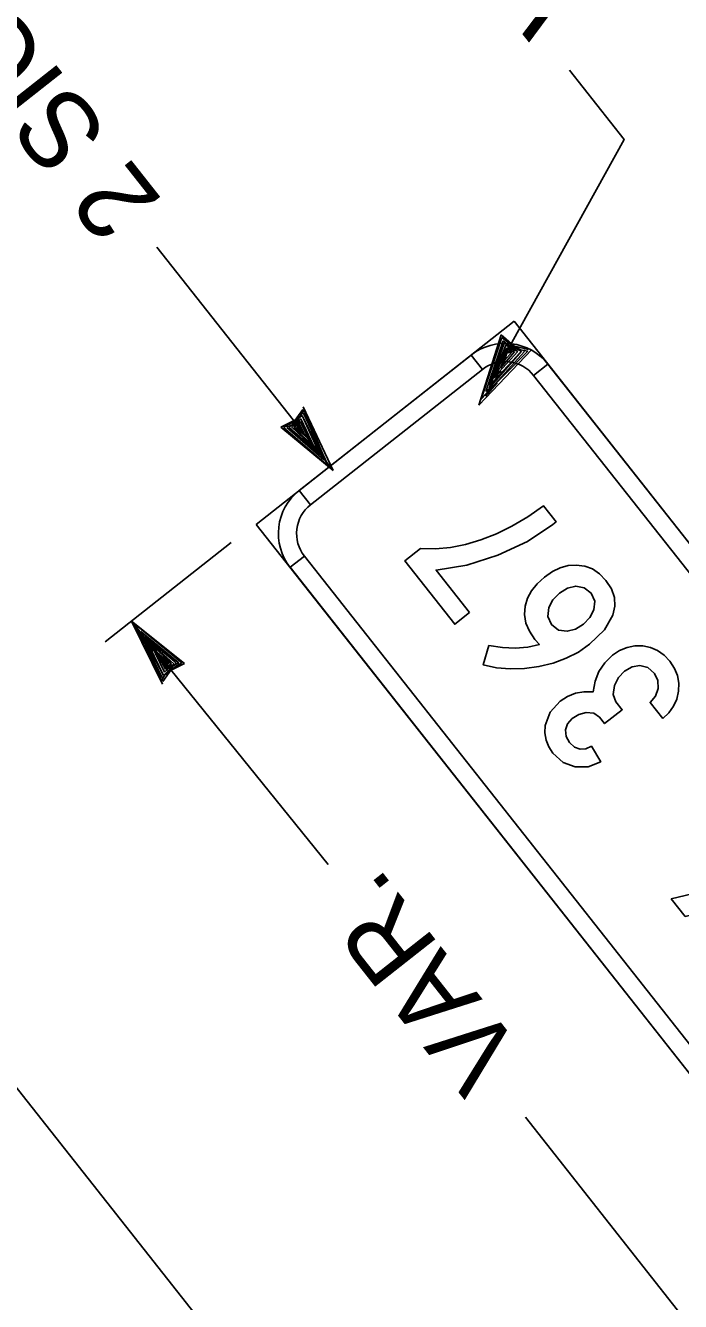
# Model space of a CAD drawing. Extents: x 672239 to 673995, y 1673540 to 1675195.
# Drawn here: x 672345.2 to 672381.1, y 1674877.9 to 1674947.8 of the extents above; entities that cross this region are included whole.
import ezdxf

# ---------------------------------------------------------------- set-up
doc = ezdxf.new("R2010")
doc.units = 0
for name, color, linetype in [('C-ALGN-SYMB', 7, 'Continuous'), ('C-ANNO-SYMB', 7, 'Continuous'), ('C-HELI-SIDE', 7, 'Continuous')]:
    doc.layers.add(name, color=color, linetype=linetype)

msp = doc.modelspace()

# ---------------------------------------------------------------- linework, layer by layer
at = {"layer": 'C-ALGN-SYMB'}
for p, q in [((672362.095, 1674923.445), (672352.437, 1674935.696)), ((672370.092, 1674927.027), (672371.308, 1674930.893)), ((672370.221, 1674927.352), (672371.348, 1674930.735)), ((672370.47, 1674927.77), (672371.412, 1674930.563)), ((672370.653, 1674927.957), (672371.559, 1674930.31)), ((672370.677, 1674928.111), (672371.465, 1674930.43)), ((672371.308, 1674930.893), (672372.005, 1674930.276)), ((672371.348, 1674930.735), (672371.917, 1674930.295)), ((672371.412, 1674930.563), (672371.654, 1674930.353)), ((672371.465, 1674930.43), (672372.431, 1674929.988)), ((672371.559, 1674930.31), (672372.226, 1674929.977)), ((672371.654, 1674930.353), (672372.431, 1674929.988)), ((672371.917, 1674930.295), (672372.784, 1674930.077)), ((672372.005, 1674930.276), (672372.372, 1674930.056)), ((672372.984, 1674930.076), (672370.092, 1674927.027)), ((672372.582, 1674929.962), (672370.251, 1674927.401)), ((672372.765, 1674929.988), (672370.378, 1674927.557)), ((672372.431, 1674929.988), (672370.653, 1674927.957)), ((672372.431, 1674929.988), (672370.677, 1674928.111)), ((672370.984, 1674928.626), (672371.56, 1674930.142)), ((672372.226, 1674929.977), (672370.984, 1674928.626)), ((672371.272, 1674929.051), (672371.574, 1674929.999)), ((672372.045, 1674929.953), (672371.272, 1674929.051)), ((672371.614, 1674930.178), (672371.398, 1674929.209)), ((672371.916, 1674929.961), (672371.497, 1674929.483)), ((672371.497, 1674929.483), (672371.634, 1674929.933)), ((672371.56, 1674930.142), (672372.045, 1674929.953)), ((672371.574, 1674929.999), (672371.916, 1674929.961)), ((672372.102, 1674930.05), (672371.614, 1674930.178)), ((672371.634, 1674929.933), (672371.743, 1674929.899)), ((672371.743, 1674929.899), (672372.102, 1674930.05)), ((672372.372, 1674930.056), (672372.765, 1674929.988)), ((672372.536, 1674930.056), (672372.582, 1674929.962)), ((672371.18, 1674929.007), (672370.949, 1674928.512)), ((672370.949, 1674928.512), (672371.31, 1674928.894)), ((672371.398, 1674929.209), (672371.18, 1674929.007)), ((672370.45, 1674927.512), (672371.096, 1674928.257)), ((672371.096, 1674928.257), (672370.47, 1674927.77)), ((672359.955, 1674926.133), (672360.442, 1674926.794)), ((672360.317, 1674926.437), (672360.512, 1674926.748)), ((672360.442, 1674926.794), (672360.374, 1674926.576)), ((672360.464, 1674926.941), (672362.095, 1674923.445)), ((672360.512, 1674926.748), (672361.744, 1674923.873)), ((672359.235, 1674925.826), (672360.003, 1674926.202)), ((672359.383, 1674925.804), (672359.955, 1674926.133)), ((672359.683, 1674925.797), (672360.395, 1674926.463)), ((672359.814, 1674925.931), (672360.395, 1674926.463)), ((672359.818, 1674925.835), (672360.333, 1674926.285)), ((672360.228, 1674926.206), (672359.949, 1674925.836)), ((672359.961, 1674925.777), (672360.29, 1674926.124)), ((672360.003, 1674926.202), (672360.317, 1674926.437)), ((672360.087, 1674925.739), (672360.238, 1674926.017)), ((672360.231, 1674925.848), (672360.228, 1674926.206)), ((672360.238, 1674926.017), (672360.499, 1674925.495)), ((672360.29, 1674926.124), (672360.787, 1674925.153)), ((672360.333, 1674926.285), (672361.048, 1674924.76)), ((672360.374, 1674926.576), (672360.47, 1674926.583)), ((672360.395, 1674926.463), (672361.378, 1674924.319)), ((672360.395, 1674926.463), (672361.5, 1674924.245)), ((672360.47, 1674926.583), (672361.833, 1674923.71)), ((672362.095, 1674923.445), (672359.235, 1674925.826)), ((672361.864, 1674923.667), (672359.383, 1674925.804)), ((672359.552, 1674925.798), (672359.814, 1674925.931)), ((672361.595, 1674924.024), (672359.552, 1674925.798)), ((672361.378, 1674924.319), (672359.683, 1674925.797)), ((672361.5, 1674924.245), (672359.818, 1674925.835)), ((672359.949, 1674925.836), (672360.697, 1674925.314)), ((672361.048, 1674924.76), (672359.961, 1674925.777)), ((672360.787, 1674925.153), (672360.087, 1674925.739)), ((672360.164, 1674925.767), (672360.231, 1674925.848)), ((672360.499, 1674925.495), (672360.164, 1674925.767)), ((672360.697, 1674925.314), (672360.792, 1674925.059)), ((672356.503, 1674919.493), (672349.599, 1674914.05)), ((672361.829, 1674901.826), (672351.043, 1674915.189)), ((672352.746, 1674911.727), (672351.043, 1674915.189)), ((672351.043, 1674915.189), (672353.951, 1674912.867)), ((672351.402, 1674914.768), (672351.279, 1674914.971)), ((672351.279, 1674914.971), (672353.803, 1674912.886)), ((672352.732, 1674912.085), (672351.31, 1674914.929)), ((672351.31, 1674914.929), (672351.34, 1674914.722)), ((672351.34, 1674914.722), (672351.765, 1674913.922)), ((672352.694, 1674911.919), (672351.402, 1674914.768)), ((672351.765, 1674913.922), (672351.554, 1674914.62)), ((672351.554, 1674914.62), (672353.634, 1674912.888)), ((672352.805, 1674912.206), (672351.654, 1674914.401)), ((672351.654, 1674914.401), (672353.369, 1674912.846)), ((672352.805, 1674912.206), (672351.778, 1674914.329)), ((672351.778, 1674914.329), (672353.503, 1674912.887)), ((672352.379, 1674913.602), (672352.031, 1674913.963)), ((672352.031, 1674913.963), (672352.239, 1674913.528)), ((672352.863, 1674912.385), (672352.117, 1674913.895)), ((672352.117, 1674913.895), (672353.225, 1674912.901)), ((672352.48, 1674913.348), (672352.379, 1674913.602)), ((672352.903, 1674912.548), (672352.386, 1674913.508)), ((672352.386, 1674913.508), (672353.098, 1674912.936)), ((672353.238, 1674912.842), (672352.48, 1674913.348)), ((672352.952, 1674912.655), (672352.681, 1674913.172)), ((672352.681, 1674913.172), (672353.021, 1674912.906)), ((672353.503, 1674912.887), (672352.805, 1674912.206)), ((672353.374, 1674912.75), (672352.805, 1674912.206)), ((672353.369, 1674912.846), (672352.863, 1674912.385)), ((672353.225, 1674912.901), (672352.903, 1674912.548)), ((672353.098, 1674912.936), (672352.952, 1674912.655)), ((672353.021, 1674912.906), (672352.956, 1674912.824)), ((672352.956, 1674912.824), (672352.967, 1674912.467)), ((672352.967, 1674912.467), (672353.238, 1674912.842)), ((672353.951, 1674912.867), (672353.192, 1674912.475)), ((672353.803, 1674912.886), (672353.238, 1674912.545)), ((672353.634, 1674912.888), (672353.374, 1674912.75)), ((672352.882, 1674912.234), (672352.694, 1674911.919)), ((672352.828, 1674912.093), (672352.732, 1674912.085)), ((672353.238, 1674912.545), (672352.764, 1674911.874)), ((672353.192, 1674912.475), (672352.882, 1674912.234)), ((672384.609, 1674872.797), (672372.641, 1674887.978))]:
    msp.add_line(p, q, dxfattribs=at)
msp.add_lwpolyline([(672371.332, 1674929.431), (672378.043, 1674941.605), (672375.053, 1674945.399)], dxfattribs=at)
at = {"layer": 'C-ANNO-SYMB'}
for p, q in [((672372.018, 1674931.633), (672357.882, 1674920.489)), ((672372.018, 1674931.633), (672357.882, 1674920.489)), ((672405.449, 1674889.226), (672372.018, 1674931.633)), ((672405.449, 1674889.226), (672372.018, 1674931.633)), ((672360.238, 1674922.346), (672369.662, 1674929.775)), ((672369.662, 1674929.775), (672360.238, 1674922.346)), ((672369.662, 1674929.775), (672370.281, 1674928.99)), ((672369.662, 1674929.775), (672370.281, 1674928.99)), ((672369.662, 1674929.775), (672370.281, 1674928.99)), ((672369.662, 1674929.775), (672370.281, 1674928.99)), ((672370.281, 1674928.99), (672360.857, 1674921.561)), ((672360.857, 1674921.561), (672370.281, 1674928.99)), ((672370.281, 1674928.99), (672370.281, 1674928.99)), ((672370.281, 1674928.99), (672370.281, 1674928.99)), ((672370.281, 1674928.99), (672370.281, 1674928.99)), ((672370.281, 1674928.99), (672370.281, 1674928.99)), ((672373.09, 1674928.658), (672373.875, 1674929.277)), ((672373.09, 1674928.658), (672373.875, 1674929.277)), ((672373.09, 1674928.658), (672373.875, 1674929.277)), ((672373.875, 1674929.277), (672373.09, 1674928.658)), ((672373.875, 1674929.277), (672403.592, 1674891.582)), ((672403.592, 1674891.582), (672373.875, 1674929.277)), ((672402.807, 1674890.963), (672373.09, 1674928.658)), ((672373.09, 1674928.658), (672402.807, 1674890.963)), ((672360.857, 1674921.561), (672360.238, 1674922.346)), ((672360.857, 1674921.561), (672360.238, 1674922.346)), ((672360.857, 1674921.561), (672360.238, 1674922.346)), ((672360.238, 1674922.346), (672360.857, 1674921.561)), ((672357.882, 1674920.489), (672391.314, 1674878.082)), ((672357.882, 1674920.489), (672391.314, 1674878.082)), ((672359.739, 1674918.133), (672360.525, 1674918.752)), ((672359.739, 1674918.133), (672360.525, 1674918.752)), ((672359.739, 1674918.133), (672360.525, 1674918.752)), ((672360.525, 1674918.752), (672359.739, 1674918.133)), ((672360.525, 1674918.752), (672390.242, 1674881.057)), ((672360.525, 1674918.752), (672360.525, 1674918.752)), ((672360.525, 1674918.752), (672360.525, 1674918.752)), ((672360.525, 1674918.752), (672360.525, 1674918.752)), ((672360.525, 1674918.752), (672360.525, 1674918.752)), ((672390.242, 1674881.057), (672360.525, 1674918.752)), ((672389.456, 1674880.438), (672359.739, 1674918.133)), ((672359.739, 1674918.133), (672389.456, 1674880.438))]:
    msp.add_line(p, q, dxfattribs=at)
for points in [[(672369.582, 1674915.654), (672367.746, 1674917.984), (672369.432, 1674918.26), (672371.125, 1674918.796), (672372.753, 1674919.552), (672374.145, 1674920.49), (672374.319, 1674920.637), (672373.629, 1674921.513), (672372.762, 1674920.909), (672371.9, 1674920.395), (672371.048, 1674919.969), (672370.199, 1674919.633), (672369.361, 1674919.383), (672368.529, 1674919.222), (672367.704, 1674919.15), (672366.885, 1674919.169), (672366.022, 1674918.489), (672368.765, 1674915.01)], [(672369.582, 1674915.654), (672367.746, 1674917.984), (672369.432, 1674918.26), (672371.125, 1674918.796), (672372.753, 1674919.552), (672374.145, 1674920.49), (672374.319, 1674920.637), (672373.629, 1674921.513), (672372.762, 1674920.909), (672371.9, 1674920.395), (672371.048, 1674919.969), (672370.199, 1674919.633), (672369.361, 1674919.383), (672368.529, 1674919.222), (672367.704, 1674919.15), (672366.885, 1674919.169), (672366.022, 1674918.489), (672368.765, 1674915.01)], [(672380.165, 1674909.837), (672380.505, 1674910.16), (672380.759, 1674910.52), (672380.937, 1674910.911), (672381.032, 1674911.338), (672381.048, 1674911.772), (672380.971, 1674912.193), (672380.807, 1674912.593), (672380.55, 1674912.981), (672380.236, 1674913.318), (672379.881, 1674913.571), (672379.494, 1674913.74), (672379.065, 1674913.825), (672378.631, 1674913.825), (672378.21, 1674913.738), (672377.804, 1674913.565), (672377.413, 1674913.309), (672376.988, 1674912.9), (672376.668, 1674912.428), (672376.459, 1674911.895), (672376.354, 1674911.305), (672375.848, 1674911.306), (672375.377, 1674911.224), (672374.945, 1674911.054), (672374.547, 1674910.798), (672373.997, 1674910.19), (672373.729, 1674909.459), (672373.708, 1674909.05), (672373.77, 1674908.661), (672373.917, 1674908.288), (672374.147, 1674907.933), (672374.701, 1674907.433), (672375.369, 1674907.185), (672376.082, 1674907.193), (672376.764, 1674907.469), (672376.258, 1674908.324), (672375.952, 1674908.175), (672375.633, 1674908.158), (672375.325, 1674908.272), (672375.058, 1674908.517), (672374.874, 1674908.861), (672374.838, 1674909.221), (672374.951, 1674909.558), (672375.202, 1674909.842), (672375.565, 1674910.058), (672375.964, 1674910.168), (672376.395, 1674910.134), (672376.7, 1674909.915), (672376.978, 1674909.562), (672377.944, 1674910.324), (672377.602, 1674910.758), (672377.443, 1674911.162), (672377.521, 1674911.661), (672377.742, 1674912.099), (672378.061, 1674912.439), (672378.484, 1674912.684), (672378.906, 1674912.754), (672379.339, 1674912.636), (672379.705, 1674912.315), (672379.904, 1674911.927), (672379.918, 1674911.494), (672379.77, 1674911.072), (672379.474, 1674910.713)], [(672380.165, 1674909.837), (672380.505, 1674910.16), (672380.759, 1674910.52), (672380.937, 1674910.911), (672381.032, 1674911.338), (672381.048, 1674911.772), (672380.971, 1674912.193), (672380.807, 1674912.593), (672380.55, 1674912.981), (672380.236, 1674913.318), (672379.881, 1674913.571), (672379.494, 1674913.74), (672379.065, 1674913.825), (672378.631, 1674913.825), (672378.21, 1674913.738), (672377.804, 1674913.565), (672377.413, 1674913.309), (672376.988, 1674912.9), (672376.668, 1674912.428), (672376.459, 1674911.895), (672376.354, 1674911.305), (672375.848, 1674911.306), (672375.377, 1674911.224), (672374.945, 1674911.054), (672374.547, 1674910.798), (672373.997, 1674910.19), (672373.729, 1674909.459), (672373.708, 1674909.05), (672373.77, 1674908.661), (672373.917, 1674908.288), (672374.147, 1674907.933), (672374.701, 1674907.433), (672375.369, 1674907.185), (672376.082, 1674907.193), (672376.764, 1674907.469), (672376.258, 1674908.324), (672375.952, 1674908.175), (672375.633, 1674908.158), (672375.325, 1674908.272), (672375.058, 1674908.517), (672374.874, 1674908.861), (672374.838, 1674909.221), (672374.951, 1674909.558), (672375.202, 1674909.842), (672375.565, 1674910.058), (672375.964, 1674910.168), (672376.395, 1674910.134), (672376.7, 1674909.915), (672376.978, 1674909.562), (672377.944, 1674910.324), (672377.602, 1674910.758), (672377.443, 1674911.162), (672377.521, 1674911.661), (672377.742, 1674912.099), (672378.061, 1674912.439), (672378.484, 1674912.684), (672378.906, 1674912.754), (672379.339, 1674912.636), (672379.705, 1674912.315), (672379.904, 1674911.927), (672379.918, 1674911.494), (672379.77, 1674911.072), (672379.474, 1674910.713)], [(672381.395, 1674898.989), (672384.395, 1674899.691), (672383.028, 1674896.917), (672383.772, 1674895.974), (672385.932, 1674900.165), (672388.723, 1674902.366), (672388.023, 1674903.255), (672385.231, 1674901.054), (672380.636, 1674899.951)], [(672381.395, 1674898.989), (672384.395, 1674899.691), (672383.028, 1674896.917), (672383.772, 1674895.974), (672385.932, 1674900.165), (672388.723, 1674902.366), (672388.023, 1674903.255), (672385.231, 1674901.054), (672380.636, 1674899.951)]]:
    msp.add_lwpolyline(points, close=True, dxfattribs=at)
for points in [[(672370.628, 1674913.843), (672370.323, 1674912.784), (672371.057, 1674912.626), (672371.811, 1674912.559), (672372.585, 1674912.578), (672373.379, 1674912.687), (672374.157, 1674912.875), (672374.879, 1674913.144), (672375.548, 1674913.488), (672376.157, 1674913.911), (672376.968, 1674914.697), (672377.427, 1674915.504), (672377.539, 1674915.995), (672377.514, 1674916.477), (672377.351, 1674916.949), (672377.053, 1674917.417), (672376.707, 1674917.781), (672376.322, 1674918.043), (672375.896, 1674918.204), (672375.428, 1674918.26), (672374.987, 1674918.225), (672374.549, 1674918.103), (672374.115, 1674917.896), (672373.683, 1674917.601), (672373.28, 1674917.234), (672372.965, 1674916.846), (672372.747, 1674916.435), (672372.616, 1674916.004), (672372.588, 1674915.538), (672372.665, 1674915.078), (672372.853, 1674914.623), (672373.146, 1674914.178), (672373.407, 1674913.909), (672372.763, 1674913.763), (672372.085, 1674913.702), (672371.373, 1674913.729), (672370.628, 1674913.843)], [(672370.628, 1674913.843), (672370.323, 1674912.784), (672371.057, 1674912.626), (672371.811, 1674912.559), (672372.585, 1674912.578), (672373.379, 1674912.687), (672374.157, 1674912.875), (672374.879, 1674913.144), (672375.548, 1674913.488), (672376.157, 1674913.911), (672376.968, 1674914.697), (672377.427, 1674915.504), (672377.539, 1674915.995), (672377.514, 1674916.477), (672377.351, 1674916.949), (672377.053, 1674917.417), (672376.707, 1674917.781), (672376.322, 1674918.043), (672375.896, 1674918.204), (672375.428, 1674918.26), (672374.987, 1674918.225), (672374.549, 1674918.103), (672374.115, 1674917.896), (672373.683, 1674917.601), (672373.28, 1674917.234), (672372.965, 1674916.846), (672372.747, 1674916.435), (672372.616, 1674916.004), (672372.588, 1674915.538), (672372.665, 1674915.078), (672372.853, 1674914.623), (672373.146, 1674914.178), (672373.407, 1674913.909), (672372.763, 1674913.763), (672372.085, 1674913.702), (672371.373, 1674913.729), (672370.628, 1674913.843)], [(672375.819, 1674915.015), (672375.376, 1674914.742), (672374.928, 1674914.624), (672374.448, 1674914.693), (672374.065, 1674914.997), (672373.867, 1674915.438), (672373.92, 1674915.93), (672374.141, 1674916.352), (672374.502, 1674916.72), (672374.946, 1674916.986), (672375.394, 1674917.1), (672375.864, 1674917.016), (672376.239, 1674916.711), (672376.435, 1674916.284), (672376.391, 1674915.796), (672376.174, 1674915.377), (672375.819, 1674915.015)], [(672375.819, 1674915.015), (672375.376, 1674914.742), (672374.928, 1674914.624), (672374.448, 1674914.693), (672374.065, 1674914.997), (672373.867, 1674915.438), (672373.92, 1674915.93), (672374.141, 1674916.352), (672374.502, 1674916.72), (672374.946, 1674916.986), (672375.394, 1674917.1), (672375.864, 1674917.016), (672376.239, 1674916.711), (672376.435, 1674916.284), (672376.391, 1674915.796), (672376.174, 1674915.377), (672375.819, 1674915.015)]]:
    msp.add_lwpolyline(points, dxfattribs=at)
for centre, radius, start, end in [((672371.519, 1674927.419), 3, 38.2506, 128.25081), ((672371.519, 1674927.419), 3, 38.2506, 128.25081), ((672371.519, 1674927.419), 2, 38.2506, 128.25081), ((672371.519, 1674927.419), 2, 38.2506, 128.25081), ((672362.095, 1674919.99), 3, 128.25054, 218.25075), ((672362.095, 1674919.99), 3, 128.25054, 218.25075), ((672362.095, 1674919.99), 2, 128.25054, 218.25075), ((672362.095, 1674919.99), 2, 128.25054, 218.25075)]:
    msp.add_arc(centre, radius, start, end, dxfattribs=at)
at = {"layer": 'C-HELI-SIDE'}
msp.add_lwpolyline([(672376.491, 1674849.308), (672302.961, 1674942.578), (672280.008, 1674924.484), (672353.538, 1674831.213)], close=True, dxfattribs=at)

# ---------------------------------------------------------------- texts
at = {"layer": 'C-ALGN-SYMB'}
for s, height, p in [('WHITE TEXT ON', 4.57469, (672376.446, 1674949.722)), ('2 SIGNS REQUIRED', 4.2, (672352.794, 1674938.234)), ('VAR.', 4.2, (672372.624, 1674891.489))]:
    msp.add_text(s, height=height, rotation=128.25054, dxfattribs=at).set_placement(p)

doc.saveas('drawing.dxf')
